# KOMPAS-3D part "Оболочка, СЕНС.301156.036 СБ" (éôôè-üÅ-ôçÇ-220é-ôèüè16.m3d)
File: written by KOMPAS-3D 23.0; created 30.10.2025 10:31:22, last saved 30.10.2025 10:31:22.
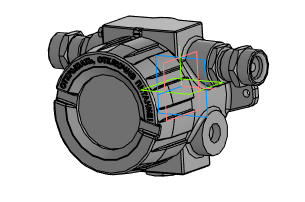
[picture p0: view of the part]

Document properties: Полное имя файла: D:\Users\5322\Documents\КОМПАС\Рабочая\ВУУК-БП-УЗА-220В(5-22)\3D\ВУУК-БП-УЗА-220В-УКБК16.m3d

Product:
- Part/product: Оболочка  | designation СЕНС.301156.036 СБ
    Масса: 3.228203

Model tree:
1. Операция без истории:1

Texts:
  СЕНС.301156.036 СБ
